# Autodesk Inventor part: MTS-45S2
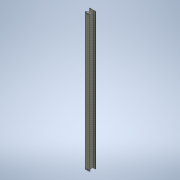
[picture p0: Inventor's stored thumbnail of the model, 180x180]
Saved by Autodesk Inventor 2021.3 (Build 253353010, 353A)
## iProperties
Created: 2021-11
Part Number: MTS-45S2
Material: Concrete, Precast
Document SubType Name: Modeling
Designer: u1426
Density: 2.40731 g/cm^3
Appearance: Smooth Precast Structural
Author: u1426
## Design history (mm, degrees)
sketch "Sketch1"
  geometry: L1 (0, 0)-(-400.05, 0); L2 (-431.8, -31.75)-(-431.8, -143.319); L3 (-390.596, -202.776)-(-208.052, -271.231); L4 (-76.2, -461.493)-(-76.2, -849.936); L5 (-267.326, -1052.777)-(-573.764, -1071.017); L6 (-609.6, -1109.05)-(-609.6, -1143); L7 (0, 0)-(400.05, 0); L8 (431.8, -31.75)-(431.8, -143.319); L9 (390.596, -202.776)-(208.052, -271.231); L10 (76.2, -461.493)-(76.2, -849.936); L11 (267.326, -1052.777)-(573.764, -1071.017); L12 (609.6, -1109.05)-(609.6, -1143); L13 (609.6, -1143)-(-609.6, -1143); L14 (431.8, -31.75)-(400.05, 0); L15 (-400.05, 0)-(-431.8, -31.75); A1 r 38.1 centre (571.5, -1109.05) between (609.6, -1109.05) and (573.764, -1071.017); A2 r 38.1 centre (-571.5, -1109.05) between (-573.764, -1071.017) and (-609.6, -1109.05); A3 r 203.2 centre (-279.4, -849.936) between (-267.326, -1052.777) and (-76.2, -849.936); A4 r 203.2 centre (279.4, -849.936) between (76.2, -849.936) and (267.326, -1052.777); A5 r 203.2 centre (279.4, -461.493) between (208.052, -271.231) and (76.2, -461.493); A6 r 203.2 centre (-279.4, -461.493) between (-76.2, -461.493) and (-208.052, -271.231); A7 r 63.5 centre (368.3, -143.319) between (390.596, -202.776) and (431.8, -143.319); A8 r 63.5 centre (-368.3, -143.319) between (-431.8, -143.319) and (-390.596, -202.776); 10 further points
  constraints: 30 end point, 20 point on line, 16 point on circle, 16 tangent, 8 centre point, 5 equal radius, 3 parallel, 3 perpendicular, 2 horizontal, 1 vertical
  dimensions: "d0" = 431.8 distance of L1.start point (-431.8, 0); "d1" = 187.325 distance of point (-431.8, 0) point (-431.8, -187.325); "d2" = 355.6 horizontal distance of point (-431.8, -187.325) point (-76.2, -320.675); "d3" = 133.35 vertical distance of point (-431.8, -187.325) point (-76.2, -320.675); "d4" = 31.75 vertical distance of point (-76.2, -1041.4) point (-609.6, -1073.15); "d5" = 69.85 distance of point (-609.6, -1073.15) L6.end; "d7" = 533.4 horizontal distance of point (-76.2, -1041.4) point (-609.6, -1073.15); "d8" = 431.8 distance of L1.start point (431.8, 0); "d9" = 187.325 distance of point (431.8, 0) point (431.8, -187.325); "d10" = 355.6 horizontal distance of point (431.8, -187.325) point (76.2, -320.675); "d11" = 133.35 vertical distance of point (431.8, -187.325) point (76.2, -320.675); "d12" = 533.4 horizontal distance of point (76.2, -1041.4) point (609.6, -1073.15); "d13" = 31.75 vertical distance of point (76.2, -1041.4) point (609.6, -1073.15); "d14" = 1143 distance between parallel lines of L1 L13; "d15" = 69.85 distance of point (609.6, -1073.15) L12.end; "d16" = 1219.2 distance between parallel lines of L6 L12 (derived); "d17" = 863.6 distance between parallel lines of L2 L8 (derived); "d18" = 152.4 distance between parallel lines of L4 L10 (derived); "d19" = 38.1 radius of A1; "d20" = 203.2 radius of A3; "d21" = 63.5 radius of A7; "d22" = 31.75 distance of L8.start point (431.8, 0); "d23" = 31.75 distance of L7.end point (431.8, 0) (= d22); "d24" = 31.75 distance of L1.end point (-431.8, 0) (= d22); "d25" = 31.75 distance of L2.start point (-431.8, 0) (= d24)
extrude "Extrusion1" new body sketch "Sketch1" distance "d26" = 27813; taper "d27" = 0 deg
sketch "Sketch4"
  geometry: L1 (-31.75, 27813)-(-31.75, 0) reference; L2 (-31.75, 27698.7)-(-6.35, 27698.7); L3 (-6.35, 27698.7)-(-6.35, 27546.3); L4 (-6.35, 27546.3)-(-31.75, 27546.3); L5 (-31.75, 27546.3)-(-31.75, 27698.7); L6 (-31.75, 114.3)-(-6.35, 114.3); L7 (-6.35, 114.3)-(-6.35, 266.7); L8 (-6.35, 266.7)-(-31.75, 266.7); L9 (-31.75, 266.7)-(-31.75, 114.3); L10 (0, 0)-(-31.75, 0) reference; L11 (-31.75, 27813)-(0, 27813) reference; 3 further points
  constraints: 16 end point, 4 parallel, 3 point on line, 2 horizontal, 2 perpendicular
  dimensions: "d40" = 25.4 distance of L3.end L4.end; "d41" = 152.4 distance of L2.end L3.end; "d42" = 152.4 distance of L7.end L6.end; "d43" = 114.3 distance between parallel lines of L6 L10; "d44" = 114.3 distance between parallel lines of L2 L11
extrude "Extrusion3" cut sketch "Sketch4" extent not by distance; stored distance "d45" = 0; taper "d46" = 0 deg
sketch "Sketch5"
  geometry: L1 (850.9, 0)-(0, 0) reference; L2 (0, 0)-(850.9, 0); L3 (825.5, -25.4)-(857.25, 6.35) reference; L4 (25.4, -25.4)-(825.5, -25.4) reference; L5 (-6.35, 6.35)-(25.4, -25.4) reference; 1 further point
  constraints: 2 end point, 1 horizontal, 1 point on line
extrude "Extrusion4" new body sketch "Sketch5" distance "d47" = 152.4; taper "d48" = 0 deg
sketch "Sketch6"
  geometry: L1 (25.4, -25.4)-(0, 0) reference; L2 (825.5, -25.4)-(25.4, -25.4) reference; L3 (850.9, 0)-(825.5, -25.4) reference; L4 (850.9, 0)-(0, 0); 2 further points
  constraints: 2 end point, 1 horizontal, 1 point on line
extrude "Extrusion5" new body sketch "Sketch6" distance "d49" = 152.4; taper "d50" = 0 deg
body "Solid1"
body "Solid2"
body "Solid3"
